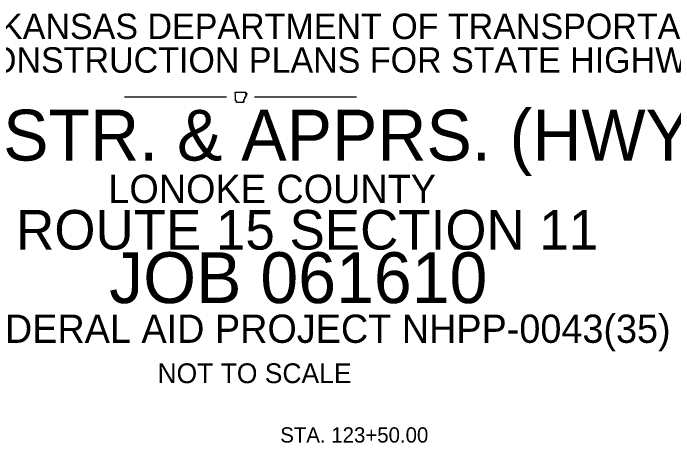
# Model space of a CAD drawing. Extents: x 1127717 to 1741049, y 2026793 to 2244711.
# Drawn here: x 1294002 to 1352440, y 2118754 to 2156746 of the extents above; entities that cross this region are included whole.
import ezdxf

# ---------------------------------------------------------------- set-up
doc = ezdxf.new("R2010")
doc.units = 0
doc.layers.add('R_Draft', color=7, linetype='Continuous')

msp = doc.modelspace()

# ---------------------------------------------------------------- linework, layer by layer
at = {"layer": 'R_Draft'}
for p, q in [((1303860.42359432, 2149337.5563738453), (1312860.4235955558, 2149337.5563738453)), ((1315360.42359432, 2149337.5563738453), (1324360.4235955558, 2149337.5563738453))]:
    msp.add_line(p, q, dxfattribs=at)
for points in [[(1313644.6151949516, 2149753.404178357), (1313917.4839450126, 2149753.2354283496), (1314156.9401949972, 2149753.7416783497), (1314439.4276950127, 2149758.129178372), (1314570.3776949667, 2149761.166678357)], [(1313664.358944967, 2149015.1229283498), (1313679.5464450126, 2149472.9416783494), (1313644.6151949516, 2149753.404178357)], [(1314529.8776949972, 2149629.372928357), (1314657.9589450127, 2149635.9541783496)], [(1314376.483944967, 2148850.4229283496), (1313758.015194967, 2148851.435428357), (1313757.6776950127, 2148987.9541783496)]]:
    msp.add_lwpolyline(points, dxfattribs=at)
for points in [[(1314591.8089449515, 2149473.4479283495), (1314592.4839450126, 2149468.5541783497), (1314589.6151950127, 2149463.322928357), (1314588.6026949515, 2149458.091678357), (1314589.108944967, 2149452.8604283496), (1314583.7089450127, 2149449.9916783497), (1314578.9839450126, 2149446.616678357), (1314581.6839449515, 2149442.5666783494), (1314586.7464450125, 2149438.854178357), (1314591.8089449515, 2149435.9854283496), (1314595.0151950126, 2149433.116678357), (1314595.8589450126, 2149426.197928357), (1314596.7026950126, 2149421.810428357), (1314598.3901950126, 2149415.7354283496), (1314599.0651949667, 2149411.5166783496), (1314596.0276949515, 2149406.4541783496), (1314592.4839450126, 2149405.4416783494), (1314588.7714450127, 2149406.622928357), (1314584.3839450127, 2149406.9604283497), (1314580.8401949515, 2149403.585428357), (1314578.3089450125, 2149398.8604283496), (1314575.7776950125, 2149394.1354283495), (1314573.9214450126, 2149390.0854283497), (1314572.0651949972, 2149385.6979283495), (1314568.3526949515, 2149380.635428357), (1314563.7964450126, 2149379.791678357), (1314558.3964450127, 2149378.441678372), (1314555.1901949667, 2149374.729178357), (1314555.6964450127, 2149368.4854283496), (1314558.733944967, 2149364.266678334), (1314561.0964449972, 2149359.0354283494), (1314562.7839449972, 2149354.4791783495), (1314561.9401949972, 2149348.7416783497), (1314559.577694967, 2149344.522928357), (1314556.5401949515, 2149341.9916783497), (1314555.1901949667, 2149336.591678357), (1314552.9964449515, 2149332.5416783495), (1314550.9714449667, 2149331.1916783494), (1314546.921444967, 2149331.529178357), (1314542.5339449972, 2149332.372928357), (1314538.8214449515, 2149332.0354283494), (1314535.2776949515, 2149330.1791783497), (1314531.733944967, 2149331.3604283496), (1314528.0214450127, 2149335.410428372), (1314524.983944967, 2149338.447928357), (1314521.6089450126, 2149339.6291783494), (1314518.0651949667, 2149337.7729283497), (1314517.390194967, 2149332.2041783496), (1314519.0776950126, 2149326.4666783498), (1314520.5964449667, 2149318.7041783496), (1314519.0776950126, 2149313.979178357), (1314518.5714450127, 2149306.2166783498)], [(1314570.3776949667, 2149761.166678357), (1314571.2214449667, 2149753.7416783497), (1314573.5839449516, 2149749.860428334), (1314573.9214450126, 2149742.7729283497), (1314576.7901950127, 2149739.7354283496), (1314581.6839449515, 2149736.697928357), (1314586.0714450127, 2149731.8041783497), (1314587.0839450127, 2149726.0666783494), (1314585.733944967, 2149720.160428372), (1314585.3964450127, 2149713.579178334), (1314584.7214449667, 2149707.841678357), (1314583.7089450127, 2149702.6104283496), (1314579.6589449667, 2149698.391678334), (1314575.7776950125, 2149695.3541783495), (1314572.2339450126, 2149691.8104283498), (1314569.7026950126, 2149688.0979283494), (1314565.3151949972, 2149684.047928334), (1314560.9276950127, 2149679.8291783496), (1314557.3839449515, 2149676.1166783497), (1314553.8401950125, 2149671.3916783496), (1314552.1526949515, 2149666.1604283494), (1314548.2714449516, 2149662.447928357), (1314545.233944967, 2149659.0729283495), (1314541.1839450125, 2149654.516678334), (1314539.1589449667, 2149649.9604283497), (1314535.2776949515, 2149644.7291783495), (1314534.4339449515, 2149639.666678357), (1314531.9026949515, 2149635.6166783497), (1314531.733944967, 2149634.9416783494)], [(1314656.1026949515, 2149635.7854283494), (1314657.9589450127, 2149635.9541783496), (1314663.6964450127, 2149629.8791783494), (1314666.2276950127, 2149624.816678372), (1314669.9401949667, 2149621.9479283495), (1314674.1589449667, 2149620.4291783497), (1314677.3651950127, 2149616.547928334), (1314679.5589449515, 2149612.3291783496), (1314678.3776949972, 2149608.6166783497), (1314673.6526950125, 2149608.2791783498), (1314668.4214450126, 2149607.4354283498), (1314663.358944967, 2149607.6041783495), (1314659.3089450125, 2149604.229178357), (1314663.0214449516, 2149599.6729283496), (1314667.9151950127, 2149595.454178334), (1314669.2651950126, 2149590.8979283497), (1314666.5651949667, 2149586.5104283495), (1314661.1651949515, 2149584.1479283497), (1314655.9339449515, 2149582.122928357), (1314651.2089450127, 2149578.0729283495), (1314649.015194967, 2149574.1916783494), (1314643.7839449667, 2149572.504178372), (1314638.3839450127, 2149570.9854283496), (1314633.6589449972, 2149570.4791783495), (1314628.2589449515, 2149569.466678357), (1314623.0276949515, 2149566.935428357), (1314620.8339450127, 2149562.5479283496), (1314621.5089450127, 2149556.3041783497), (1314621.3401949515, 2149549.722928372), (1314626.9089449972, 2149547.529178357), (1314631.8026949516, 2149547.3604283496), (1314636.5276950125, 2149544.8291783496), (1314636.0214449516, 2149541.1166783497), (1314632.4776949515, 2149536.3916783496), (1314628.2589449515, 2149532.6791783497), (1314624.0401949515, 2149530.822928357), (1314620.1589449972, 2149527.2791783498), (1314621.5089450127, 2149523.7354283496), (1314625.0526950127, 2149521.3729283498), (1314627.5839450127, 2149517.4916783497), (1314627.2464449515, 2149513.947928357), (1314623.1964449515, 2149511.4166783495), (1314618.8089449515, 2149512.4291783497), (1314615.6026950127, 2149516.6479283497), (1314611.890194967, 2149517.997928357), (1314608.6839450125, 2149519.5166783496), (1314604.9714449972, 2149517.3229283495), (1314604.9714449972, 2149512.4291783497), (1314603.6214450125, 2149507.197928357), (1314604.8026949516, 2149503.3166783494), (1314606.3214450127, 2149497.9166783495), (1314606.1526950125, 2149493.8666783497), (1314604.8026949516, 2149488.1291783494), (1314601.9339450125, 2149482.222928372), (1314598.5589450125, 2149480.3666783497), (1314597.2089450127, 2149486.779178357), (1314596.5339449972, 2149492.010428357), (1314594.5089449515, 2149495.0479283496), (1314591.8089449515, 2149495.216678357), (1314588.265194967, 2149492.685428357), (1314584.3839450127, 2149488.8041783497), (1314579.4901949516, 2149484.585428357), (1314576.6214450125, 2149480.3666783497), (1314578.1401950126, 2149475.1354283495), (1314581.8526950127, 2149473.7854283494), (1314584.7214449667, 2149474.7979283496), (1314586.2401950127, 2149478.1729283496), (1314589.108944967, 2149478.6791783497), (1314591.8089449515, 2149473.4479283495)], [(1313757.6776950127, 2148987.9541783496), (1313758.3526949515, 2148987.616678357), (1313755.1464450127, 2148989.810428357), (1313750.7589450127, 2148992.0041783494), (1313745.8651949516, 2148992.341678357), (1313739.6214450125, 2148993.1854283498), (1313734.3901950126, 2148993.691678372), (1313728.9901950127, 2148997.2354283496), (1313723.2526949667, 2148993.5229283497), (1313716.8401950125, 2148990.822928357), (1313713.1276949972, 2148993.8604283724), (1313708.2339450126, 2148991.8354283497), (1313704.8589450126, 2148992.847928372), (1313698.952694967, 2148988.7979283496), (1313693.3839450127, 2148990.3166783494), (1313689.3339449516, 2148989.135428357), (1313684.2714449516, 2148989.304178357), (1313683.2589449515, 2148995.041678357), (1313678.3651950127, 2148995.885428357), (1313674.1464449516, 2148998.247928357), (1313671.2776949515, 2149004.154178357), (1313669.2526949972, 2149008.7104283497), (1313664.358944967, 2149015.1229283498)], [(1314402.3026949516, 2149082.9604283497), (1314400.6151949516, 2149079.0791783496), (1314398.7589450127, 2149072.3291783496), (1314399.265194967, 2149066.5916783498), (1314401.7964450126, 2149061.697928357), (1314405.8464449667, 2149058.997928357), (1314410.233944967, 2149055.116678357), (1314409.8964450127, 2149049.2104283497), (1314407.3651950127, 2149047.0166783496), (1314401.4589449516, 2149048.5354283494), (1314396.9026950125, 2149050.560428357), (1314393.0214449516, 2149049.3791783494), (1314387.7901949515, 2149046.847928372), (1314383.9089449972, 2149046.3416783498), (1314384.077694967, 2149038.2416783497), (1314389.3089449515, 2149032.5041783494), (1314393.8651949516, 2149032.5041783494), (1314399.0964449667, 2149031.829178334), (1314400.9526950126, 2149025.7541783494), (1314397.9151950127, 2149020.6916783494), (1314392.8526949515, 2149018.1604283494), (1314386.4401949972, 2149021.1979283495), (1314381.8839450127, 2149024.4041783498), (1314377.327694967, 2149027.4416783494), (1314371.5901950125, 2149028.9604283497), (1314368.3839450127, 2149028.2854283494), (1314366.8651949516, 2149021.1979283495), (1314369.5651949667, 2149014.7854283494), (1314373.9526950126, 2149010.397928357), (1314378.0026949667, 2149004.6604283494), (1314377.327694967, 2149000.441678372), (1314374.2901950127, 2148999.2604283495), (1314368.890194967, 2148998.0791783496), (1314365.6839450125, 2148996.3916783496), (1314364.8401950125, 2148995.041678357), (1314366.5276950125, 2148989.304178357), (1314368.046444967, 2148983.060428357), (1314368.046444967, 2148978.3354283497), (1314366.1901949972, 2148973.947928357), (1314363.3214449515, 2148967.197928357), (1314363.6589449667, 2148962.8104283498), (1314365.6839450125, 2148960.7854283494), (1314368.2151950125, 2148961.4604283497), (1314371.5901950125, 2148963.8229283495), (1314373.7839449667, 2148966.522928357), (1314375.640194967, 2148969.8979283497), (1314379.1839450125, 2148972.7666783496), (1314383.5714450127, 2148970.2354283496), (1314384.5839450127, 2148965.004178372), (1314382.0526950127, 2148960.447928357), (1314378.5089450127, 2148958.4229283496), (1314374.1214449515, 2148956.7354283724), (1314370.9151950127, 2148953.0229283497), (1314371.7589450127, 2148948.6354283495), (1314374.2901950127, 2148946.2729283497), (1314380.5339449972, 2148947.4541783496), (1314384.7526949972, 2148949.3104283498), (1314387.1151949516, 2148951.6729283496), (1314389.9839450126, 2148954.5416783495), (1314391.5026949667, 2148957.410428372), (1314393.6964449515, 2148960.447928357), (1314397.577694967, 2148961.291678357), (1314399.4339450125, 2148958.760428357), (1314398.7589450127, 2148953.0229283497), (1314396.3964449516, 2148947.622928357), (1314393.1901949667, 2148943.066678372), (1314389.6464450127, 2148939.8604283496), (1314385.2589450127, 2148932.9416783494), (1314386.1026950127, 2148926.5291783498), (1314387.7901949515, 2148921.2979283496), (1314390.1526949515, 2148917.247928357), (1314394.2026950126, 2148918.091678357), (1314398.7589450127, 2148918.597928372), (1314401.4589449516, 2148916.404178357), (1314401.1214450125, 2148911.6791783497), (1314397.7464450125, 2148907.122928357), (1314394.5401949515, 2148902.7354283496), (1314392.8526949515, 2148896.660428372), (1314393.5276950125, 2148892.4416783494), (1314393.5276950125, 2148888.560428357), (1314392.1776949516, 2148884.341678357), (1314389.8151949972, 2148881.9791783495), (1314383.5714450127, 2148882.1479283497), (1314376.9901950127, 2148882.822928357), (1314373.4464450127, 2148880.7979283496), (1314374.1214449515, 2148875.0604283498), (1314378.0026949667, 2148870.841678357), (1314380.702694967, 2148868.647928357), (1314384.5839450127, 2148863.9229283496), (1314386.2714449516, 2148860.0416783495), (1314385.7651950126, 2148856.666678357), (1314383.4026949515, 2148853.797928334), (1314376.483944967, 2148850.4229283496)], [(1314518.5714450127, 2149306.2166783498), (1314514.6901949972, 2149301.322928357), (1314508.9526950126, 2149304.3604283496), (1314508.9526950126, 2149308.4104283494), (1314509.7964450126, 2149312.629178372), (1314507.7714450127, 2149315.3291783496), (1314504.2276950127, 2149314.147928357), (1314504.2276950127, 2149308.916678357), (1314503.8901950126, 2149303.8541783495), (1314502.8776949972, 2149296.5979283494), (1314505.2401949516, 2149294.404178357), (1314510.6401950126, 2149293.729178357), (1314514.5214449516, 2149292.716678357), (1314516.8839450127, 2149288.8354283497), (1314516.7151950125, 2149284.110428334), (1314514.8589450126, 2149279.5541783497), (1314512.1589449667, 2149275.8416783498), (1314507.9401949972, 2149274.4916783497), (1314504.5651949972, 2149276.6854283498), (1314503.2151949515, 2149281.0729283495), (1314501.6964450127, 2149284.9541783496), (1314498.827694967, 2149287.8229283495), (1314495.7901950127, 2149284.616678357), (1314495.1151950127, 2149278.7104283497), (1314495.2839449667, 2149273.6479283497), (1314495.2839449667, 2149266.7291783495), (1314499.671444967, 2149262.1729283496), (1314502.3714449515, 2149256.9416783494), (1314501.5276949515, 2149252.2166783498), (1314498.3214449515, 2149246.647928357), (1314496.9714449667, 2149241.7541783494), (1314495.6214450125, 2149235.1729283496), (1314495.7901950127, 2149227.916678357), (1314494.608944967, 2149220.8291783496), (1314492.2464449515, 2149216.1041783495), (1314487.858944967, 2149212.2229283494), (1314484.9901949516, 2149209.691678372), (1314482.6276949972, 2149207.1604283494), (1314481.4464449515, 2149202.097928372), (1314480.6026949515, 2149198.5541783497), (1314477.3964450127, 2149194.3354283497), (1314474.8651949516, 2149193.9979283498), (1314472.8401949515, 2149195.685428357), (1314472.1651950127, 2149198.5541783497), (1314472.1651950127, 2149201.422928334), (1314470.8151949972, 2149204.291678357), (1314466.5964449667, 2149205.4729283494), (1314463.2214449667, 2149205.3041783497), (1314461.7026950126, 2149202.9416783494), (1314463.8964450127, 2149196.3604283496), (1314464.7401950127, 2149192.1416783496), (1314463.5589449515, 2149186.4041783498), (1314464.233944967, 2149185.7291783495), (1314458.1589449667, 2149182.5229283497), (1314453.2651950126, 2149182.0166783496), (1314449.2151949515, 2149180.835428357), (1314445.3339449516, 2149178.3041783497), (1314443.4776950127, 2149174.591678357), (1314440.7776949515, 2149171.5541783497), (1314438.4151949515, 2149168.685428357), (1314435.2089450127, 2149167.3354283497), (1314431.6651950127, 2149168.010428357), (1314426.9401949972, 2149168.5166783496), (1314424.2401949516, 2149165.141678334), (1314425.0839449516, 2149160.247928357), (1314428.2901950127, 2149157.379178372), (1314433.0151950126, 2149156.0291783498), (1314437.9089449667, 2149156.3666783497), (1314442.6339450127, 2149156.8729283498), (1314447.0214450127, 2149154.5104283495), (1314446.1776949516, 2149149.954178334), (1314441.9589450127, 2149147.7604283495), (1314435.7151950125, 2149147.0854283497), (1314430.6526950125, 2149147.591678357), (1314424.5776950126, 2149146.2416783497), (1314421.5401949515, 2149142.360428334), (1314423.2276949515, 2149136.4541783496), (1314429.8089450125, 2149134.0916783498), (1314432.8464449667, 2149128.522928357), (1314433.0151950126, 2149123.291678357), (1314430.8214450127, 2149116.372928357), (1314427.7839449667, 2149113.166678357), (1314421.8776949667, 2149111.816678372), (1314417.3214449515, 2149110.9729283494), (1314416.6464449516, 2149103.2104283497), (1314414.6214449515, 2149099.3291783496), (1314411.077694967, 2149098.147928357), (1314406.015194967, 2149100.6791783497), (1314402.9776950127, 2149101.8604283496), (1314399.265194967, 2149103.5479283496), (1314394.5401949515, 2149106.416678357), (1314390.9964450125, 2149105.910428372), (1314392.0089449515, 2149098.485428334), (1314392.3464449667, 2149098.147928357), (1314396.3964449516, 2149092.5791783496), (1314400.4464450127, 2149088.1916783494), (1314402.3026949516, 2149082.9604283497)]]:
    msp.add_spline(points, degree=3, dxfattribs=at)

# ---------------------------------------------------------------- texts
for s, height, p in [('ARKANSAS DEPARTMENT OF TRANSPORTATION', 2249.999999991, (1288655.9452484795, 2154462.5563732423)), ('CONSTRUCTION PLANS FOR STATE HIGHWAY', 2249.999999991, (1289777.2543035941, 2151482.5563732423)), ('I-40 STR. & APPRS. (HWY. 15) (S)', 4500, (1281068.100760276, 2143712.556373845)), ('LONOKE COUNTY', 2500, (1302421.4472169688, 2139962.556373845)), ('ROUTE 15 SECTION 11', 3499.9999999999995, (1294258.0613902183, 2135840.4989236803)), ('JOB 061610', 4500, (1302492.313358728, 2131107.599422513)), ('FEDERAL AID PROJECT NHPP-0043(35)', 2500, (1288996.2503665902, 2127591.5978559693)), ('NOT TO SCALE', 1749.9999999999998, (1306765.9354059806, 2124029.1500511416)), ('STA. 123+50.00', 1349.9999999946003, (1317625.6824788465, 2118772.688250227))]:
    msp.add_text(s, height=height, dxfattribs=at).set_placement(p)

doc.saveas('drawing.dxf')
